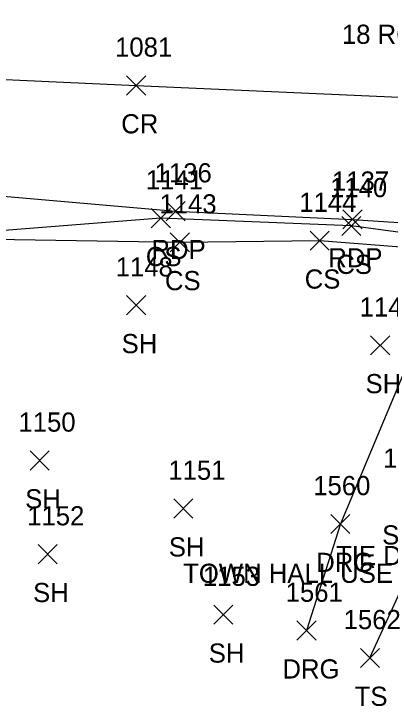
# Model space of a CAD drawing. Extents: x 1657482 to 1661439, y 647981 to 649041.
# Drawn here: x 1659806 to 1659845.2, y 648032.5 to 648104.7 of the extents above; entities that cross this region are included whole.
import ezdxf

# ---------------------------------------------------------------- set-up
doc = ezdxf.new("R2010")
doc.units = 0
for name, color, linetype in [('C_C', 7, 'Continuous'), ('D_C', 7, 'Continuous'), ('L_A', 7, 'Continuous'), ('L_I', 7, 'Continuous'), ('L_TIC', 7, 'Continuous'), ('LELB', 7, 'Continuous'), ('P_A', 7, 'Continuous'), ('P_I', 7, 'Continuous'), ('P_TIC', 7, 'Continuous'), ('PET', 7, 'Continuous'), ('PRC', 7, 'Continuous'), ('R_A', 7, 'Continuous'), ('R_I', 7, 'Continuous'), ('R_TIC', 7, 'Continuous'), ('RDG', 7, 'Continuous'), ('S_A', 7, 'Continuous'), ('S_C', 7, 'Continuous'), ('S_I', 7, 'Continuous')]:
    doc.layers.add(name, color=color, linetype=linetype)

msp = doc.modelspace()

# ---------------------------------------------------------------- linework, layer by layer
at = {"layer": 'L_TIC'}
for points in [[(1659820.287, 648082.368), (1659822.287, 648084.368)], [(1659822.287, 648082.368), (1659820.287, 648084.368)], [(1659840.119, 648081.553), (1659842.119, 648083.553)], [(1659842.119, 648081.553), (1659840.119, 648083.553)], [(1659822.275, 648079.854), (1659824.275, 648081.854)], [(1659824.275, 648079.854), (1659822.275, 648081.854)], [(1659836.829, 648080.022), (1659838.829, 648082.022)], [(1659838.829, 648080.022), (1659836.829, 648082.022)], [(1659817.719, 648073.29), (1659819.719, 648075.29)], [(1659819.719, 648073.29), (1659817.719, 648075.29)], [(1659843.116, 648069.114), (1659845.116, 648071.114)], [(1659845.116, 648069.114), (1659843.116, 648071.114)], [(1659807.68, 648057.108), (1659809.68, 648059.108)], [(1659809.68, 648057.108), (1659807.68, 648059.108)], [(1659822.634, 648052.094), (1659824.634, 648054.094)], [(1659824.634, 648052.094), (1659822.634, 648054.094)], [(1659808.504, 648047.338), (1659810.504, 648049.338)], [(1659810.504, 648047.338), (1659808.504, 648049.338)], [(1659826.792, 648041.028), (1659828.792, 648043.028)], [(1659828.792, 648041.028), (1659826.792, 648043.028)], [(1659842.067, 648036.519), (1659844.067, 648038.519)], [(1659844.067, 648036.519), (1659842.067, 648038.519)]]:
    msp.add_lwpolyline(points, dxfattribs=at)
at = {"layer": 'LELB'}
for points in [[(1659855.388, 648078.995), (1659852.388, 648081.027), (1659841.119, 648082.553), (1659821.287, 648083.368), (1659795.275, 648081.325), (1659823.275, 648080.854), (1659837.829, 648081.022), (1659847.593, 648080.286), (1659853.195, 648078.545)], [(1659843.067, 648037.519), (1659849.136, 648050.781), (1659854.348, 648061.065), (1659857.118, 648074.796), (1659862.539, 648074.991), (1659866.841, 648074.821), (1659875.346, 648073.306), (1659881.621, 648071.832), (1659886.035, 648069.24), (1659889.385, 648068.66)]]:
    msp.add_lwpolyline(points, dxfattribs=at)
at = {"layer": 'P_TIC'}
for points in [[(1659817.732, 648096.206), (1659819.732, 648098.206)], [(1659819.732, 648096.206), (1659817.732, 648098.206)], [(1659821.829, 648083.094), (1659823.829, 648085.094)], [(1659823.829, 648083.094), (1659821.829, 648085.094)], [(1659840.236, 648082.238), (1659842.236, 648084.238)], [(1659842.236, 648082.238), (1659840.236, 648084.238)]]:
    msp.add_lwpolyline(points, dxfattribs=at)
at = {"layer": 'PET'}
msp.add_lwpolyline([(1659799.28, 648086.136), (1659822.829, 648084.094), (1659841.236, 648083.238), (1659849.285, 648082.699), (1659853.297, 648081.633), (1659863.28, 648081.701), (1659871.418, 648082.62), (1659885.552, 648085.022), (1659891.684, 648086.345), (1659901.533, 648088.7), (1659915.482, 648092.509), (1659918.893, 648092.262), (1659919.908, 648093.139), (1659925.791, 648090.399), (1659928.096, 648095.554), (1659935.247, 648097.751), (1659946.62, 648102.053), (1659958.358, 648107.252), (1659972.375, 648114.357), (1659985.018, 648121.317), (1659986.135, 648122.233), (1660002.916, 648130.398), (1660023.122, 648141.511)], dxfattribs=at)
at = {"layer": 'PRC'}
msp.add_lwpolyline([(1659666.144, 648110.534), (1659699.551, 648107.376), (1659729.526, 648104.331), (1659765.503, 648101.141), (1659792.988, 648098.376), (1659818.732, 648097.206), (1659849.225, 648095.841), (1659870.331, 648096.361), (1659894.597, 648099.456), (1659913.112, 648103.656), (1659935.294, 648110.794), (1659956.941, 648119.929), (1659978.865, 648130.6), (1660002.085, 648142.328), (1660031.609, 648158.263), (1660061.231, 648174.691), (1660097.076, 648195.768), (1660113.884, 648205.485), (1660151.727, 648227.302), (1660188.688, 648248.658)], dxfattribs=at)
at = {"layer": 'R_TIC'}
for points in [[(1659838.984, 648050.485), (1659840.984, 648052.485)], [(1659840.984, 648050.485), (1659838.984, 648052.485)], [(1659835.461, 648039.373), (1659837.461, 648041.373)], [(1659837.461, 648039.373), (1659835.461, 648041.373)]]:
    msp.add_lwpolyline(points, dxfattribs=at)
at = {"layer": 'RDG'}
msp.add_lwpolyline([(1659859.967, 648078.251), (1659854.704, 648076.756), (1659850.388, 648073.521), (1659847.71, 648069.926), (1659839.984, 648051.485), (1659836.461, 648040.373)], dxfattribs=at)

# ---------------------------------------------------------------- texts
at = {"layer": 'C_C'}
msp.add_text('TIE DIST=18.12 ON CORNER BOARD', height=2, dxfattribs=at).set_placement((1659839.537, 648047.189))
at = {"layer": 'D_C'}
msp.add_text('18 RCP', height=2, dxfattribs=at).set_placement((1659840.141, 648101.54))
at = {"layer": 'L_A'}
for s, p in [('CS', (1659819.728, 648078.368)), ('CS', (1659839.56, 648077.553)), ('CS', (1659821.716, 648075.854)), ('CS', (1659836.27, 648076.022)), ('SH', (1659817.207, 648069.29)), ('SH', (1659842.604, 648065.114)), ('SH', (1659807.168, 648053.108)), ('SH', (1659822.122, 648048.094)), ('SH', (1659807.992, 648043.338)), ('SH', (1659826.28, 648037.028)), ('TS', (1659841.476, 648032.519))]:
    msp.add_text(s, height=2, dxfattribs=at).set_placement(p)
at = {"layer": 'L_I'}
for s, p in [('1141', (1659819.728, 648086.368)), ('1140', (1659838.907, 648085.553)), ('1143', (1659821.149, 648083.854)), ('1144', (1659835.703, 648084.022)), ('1148', (1659816.594, 648077.29)), ('1147', (1659841.991, 648073.114)), ('1150', (1659806.468, 648061.108)), ('1151', (1659822.075, 648056.094)), ('1152', (1659807.378, 648051.338)), ('1153', (1659825.666, 648045.028)), ('1562', (1659840.327, 648040.519))]:
    msp.add_text(s, height=2, dxfattribs=at).set_placement(p)
at = {"layer": 'P_A'}
for s, p in [('CR', (1659817.165, 648092.206)), ('RDP', (1659820.317, 648079.094)), ('RDP', (1659838.724, 648078.238))]:
    msp.add_text(s, height=2, dxfattribs=at).set_placement(p)
at = {"layer": 'P_I'}
for s, p in [('1081', (1659816.527, 648100.206)), ('1136', (1659820.648, 648087.094)), ('1137', (1659839.11, 648086.238))]:
    msp.add_text(s, height=2, dxfattribs=at).set_placement(p)
at = {"layer": 'R_A'}
for p in [(1659837.472, 648046.485), (1659833.949, 648035.373)]:
    msp.add_text('DRG', height=2, dxfattribs=at).set_placement(p)
at = {"layer": 'R_I'}
for s, p in [('1560', (1659837.157, 648054.485)), ('1561', (1659834.288, 648043.373))]:
    msp.add_text(s, height=2, dxfattribs=at).set_placement(p)
at = {"layer": 'S_A'}
msp.add_text('SIGN', height=2, dxfattribs=at).set_placement((1659844.331, 648049.342))
at = {"layer": 'S_C'}
msp.add_text('TOWN HALL USE PARKING ONLY', height=2, dxfattribs=at).set_placement((1659823.615, 648045.342))
at = {"layer": 'S_I'}
msp.add_text('1564', height=2, dxfattribs=at).set_placement((1659844.433, 648057.342))

doc.saveas('drawing.dxf')
